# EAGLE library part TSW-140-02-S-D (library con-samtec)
THROUGH-HOLE .025" SQ POST HEADER Source: Samtec TSW.pdf
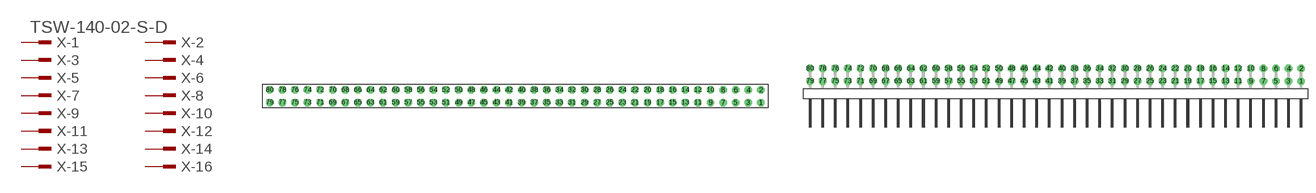
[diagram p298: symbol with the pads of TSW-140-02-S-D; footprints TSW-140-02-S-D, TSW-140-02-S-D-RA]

Designator prefix X; gates -1=MPINV -2=MPIN -3=MPIN -4=MPIN -5=MPIN -6=MPIN -7=MPIN -8=MPIN -9=MPIN -10=MPIN -11=MPIN -12=MPIN -13=MPIN -14=MPIN -15=MPIN -16=MPIN -17=MPIN -18=MPIN -19=MPIN -20=MPIN -21=MPIN -22=MPIN -23=MPIN -24=MPIN -25=MPIN -26=MPIN -27=MPIN -28=MPIN -29=MPIN -30=MPIN -31=MPIN -32=MPIN -33=MPIN -34=MPIN -35=MPIN -36=MPIN -37=MPIN -38=MPIN -39=MPIN -40=MPIN -41=MPIN -42=MPIN -43=MPIN -44=MPIN -45=MPIN -46=MPIN -47=MPIN -48=MPIN -49=MPIN -50=MPIN -51=MPIN -52=MPIN -53=MPIN -54=MPIN -55=MPIN -56=MPIN -57=MPIN -58=MPIN -59=MPIN -60=MPIN -61=MPIN -62=MPIN -63=MPIN -64=MPIN -65=MPIN -66=MPIN -67=MPIN -68=MPIN -69=MPIN -70=MPIN -71=MPIN -72=MPIN -73=MPIN -74=MPIN -75=MPIN -76=MPIN -77=MPIN -78=MPIN -79=MPIN -80=MPIN

## TSW-140-02-S-D (OC_FARNELL: unknown; OC_NEWARK: unknown)  [TSW-140-02-S-D]
1  -1:1  pas
2  -2:1  pas
3  -3:1  pas
4  -4:1  pas
5  -5:1  pas
6  -6:1  pas
7  -7:1  pas
8  -8:1  pas
9  -9:1  pas
10  -10:1  pas
11  -11:1  pas
12  -12:1  pas
13  -13:1  pas
14  -14:1  pas
15  -15:1  pas
16  -16:1  pas
17  -17:1  pas
18  -18:1  pas
19  -19:1  pas
20  -20:1  pas
21  -21:1  pas
22  -22:1  pas
23  -23:1  pas
24  -24:1  pas
25  -25:1  pas
26  -26:1  pas
27  -27:1  pas
28  -28:1  pas
29  -29:1  pas
30  -30:1  pas
31  -31:1  pas
32  -32:1  pas
33  -33:1  pas
34  -34:1  pas
35  -35:1  pas
36  -36:1  pas
37  -37:1  pas
38  -38:1  pas
39  -39:1  pas
40  -40:1  pas
41  -41:1  pas
42  -42:1  pas
43  -43:1  pas
44  -44:1  pas
45  -45:1  pas
46  -46:1  pas
47  -47:1  pas
48  -48:1  pas
49  -49:1  pas
50  -50:1  pas
51  -51:1  pas
52  -52:1  pas
53  -53:1  pas
54  -54:1  pas
55  -55:1  pas
56  -56:1  pas
57  -57:1  pas
58  -58:1  pas
59  -59:1  pas
60  -60:1  pas
61  -61:1  pas
62  -62:1  pas
63  -63:1  pas
64  -64:1  pas
65  -65:1  pas
66  -66:1  pas
67  -67:1  pas
68  -68:1  pas
69  -69:1  pas
70  -70:1  pas
71  -71:1  pas
72  -72:1  pas
73  -73:1  pas
74  -74:1  pas
75  -75:1  pas
76  -76:1  pas
77  -77:1  pas
78  -78:1  pas
79  -79:1  pas
80  -80:1  pas

## TSW-140-02-S-D-RA (OC_FARNELL: unknown; OC_NEWARK: unknown)  [TSW-140-02-S-D-RA]
Pads as for TSW-140-02-S-D

## Footprint TSW-140-02-S-D (pad centres in mm)
THROUGH-HOLE .025" SQ POST HEADER Source: Samtec TSW.pdf
drill 1 pad 1.5 octagon: 1 49.53,-1.27; 2 49.53,1.27; 3 46.99,-1.27; 4 46.99,1.27; 5 44.45,-1.27; 6 44.45,1.27; 7 41.91,-1.27; 8 41.91,1.27; 9 39.37,-1.27; 10 39.37,1.27; 11 36.83,-1.27; 12 36.83,1.27; 13 34.29,-1.27; 14 34.29,1.27; 15 31.75,-1.27; 16 31.75,1.27; 17 29.21,-1.27; 18 29.21,1.27; 19 26.67,-1.27; 20 26.67,1.27; 21 24.13,-1.27; 22 24.13,1.27; 23 21.59,-1.27; 24 21.59,1.27; 25 19.05,-1.27; 26 19.05,1.27; 27 16.51,-1.27; 28 16.51,1.27; 29 13.97,-1.27; 30 13.97,1.27; 31 11.43,-1.27; 32 11.43,1.27; 33 8.89,-1.27; 34 8.89,1.27; 35 6.35,-1.27; 36 6.35,1.27; 37 3.81,-1.27; 38 3.81,1.27; 39 1.27,-1.27; 40 1.27,1.27; 41 -1.27,-1.27; 42 -1.27,1.27; 43 -3.81,-1.27; 44 -3.81,1.27; 45 -6.35,-1.27; 46 -6.35,1.27; 47 -8.89,-1.27; 48 -8.89,1.27; 49 -11.43,-1.27; 50 -11.43,1.27; 51 -13.97,-1.27; 52 -13.97,1.27; 53 -16.51,-1.27; 54 -16.51,1.27; 55 -19.05,-1.27; 56 -19.05,1.27; 57 -21.59,-1.27; 58 -21.59,1.27; 59 -24.13,-1.27; 60 -24.13,1.27; 61 -26.67,-1.27; 62 -26.67,1.27; 63 -29.21,-1.27; 64 -29.21,1.27; 65 -31.75,-1.27; 66 -31.75,1.27; 67 -34.29,-1.27; 68 -34.29,1.27; 69 -36.83,-1.27; 70 -36.83,1.27; 71 -39.37,-1.27; 72 -39.37,1.27; 73 -41.91,-1.27; 74 -41.91,1.27; 75 -44.45,-1.27; 76 -44.45,1.27; 77 -46.99,-1.27; 78 -46.99,1.27; 79 -49.53,-1.27; 80 -49.53,1.27

## Footprint TSW-140-02-S-D-RA (pad centres in mm)
THROUGH-HOLE .025" SQ POST HEADER Source: Samtec TSW.pdf
drill 1 pad 1.5 octagon: 1 49.53,1.524; 2 49.53,4.064; 3 46.99,1.524; 4 46.99,4.064; 5 44.45,1.524; 6 44.45,4.064; 7 41.91,1.524; 8 41.91,4.064; 9 39.37,1.524; 10 39.37,4.064; 11 36.83,1.524; 12 36.83,4.064; 13 34.29,1.524; 14 34.29,4.064; 15 31.75,1.524; 16 31.75,4.064; 17 29.21,1.524; 18 29.21,4.064; 19 26.67,1.524; 20 26.67,4.064; 21 24.13,1.524; 22 24.13,4.064; 23 21.59,1.524; 24 21.59,4.064; 25 19.05,1.524; 26 19.05,4.064; 27 16.51,1.524; 28 16.51,4.064; 29 13.97,1.524; 30 13.97,4.064; 31 11.43,1.524; 32 11.43,4.064; 33 8.89,1.524; 34 8.89,4.064; 35 6.35,1.524; 36 6.35,4.064; 37 3.81,1.524; 38 3.81,4.064; 39 1.27,1.524; 40 1.27,4.064; 41 -1.27,1.524; 42 -1.27,4.064; 43 -3.81,1.524; 44 -3.81,4.064; 45 -6.35,1.524; 46 -6.35,4.064; 47 -8.89,1.524; 48 -8.89,4.064; 49 -11.43,1.524; 50 -11.43,4.064; 51 -13.97,1.524; 52 -13.97,4.064; 53 -16.51,1.524; 54 -16.51,4.064; 55 -19.05,1.524; 56 -19.05,4.064; 57 -21.59,1.524; 58 -21.59,4.064; 59 -24.13,1.524; 60 -24.13,4.064; 61 -26.67,1.524; 62 -26.67,4.064; 63 -29.21,1.524; 64 -29.21,4.064; 65 -31.75,1.524; 66 -31.75,4.064; 67 -34.29,1.524; 68 -34.29,4.064; 69 -36.83,1.524; 70 -36.83,4.064; 71 -39.37,1.524; 72 -39.37,4.064; 73 -41.91,1.524; 74 -41.91,4.064; 75 -44.45,1.524; 76 -44.45,4.064; 77 -46.99,1.524; 78 -46.99,4.064; 79 -49.53,1.524; 80 -49.53,4.064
